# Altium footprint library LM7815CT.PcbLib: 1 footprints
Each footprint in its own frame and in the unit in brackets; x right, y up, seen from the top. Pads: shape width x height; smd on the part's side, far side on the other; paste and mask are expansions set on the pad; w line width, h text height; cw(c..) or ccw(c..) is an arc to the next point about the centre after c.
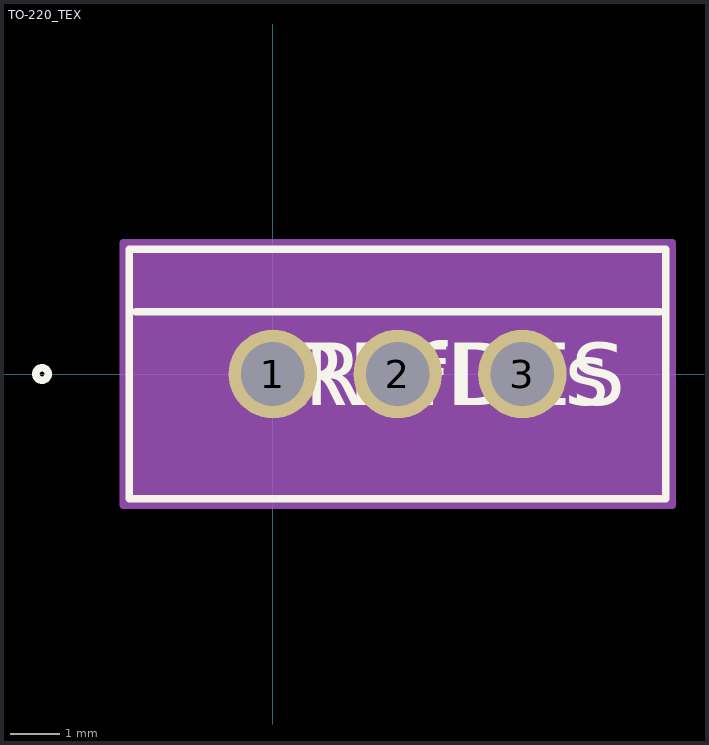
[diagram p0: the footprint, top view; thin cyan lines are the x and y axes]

## TO-220_TEX [mil]
pads (3):
  round 71 / inner round 60 / far side round 71 hole 51 paste-35.5 mask+0: 1(0,0) 2(100,0) 3(200,0)
Top Overlay:
  circle w6: c-185.04,0 r5
  lines w6: -110.04,50.08 310.04,50.08 ; -115.04,-100.08 315.04,-100.08 315.04,100.08 -115.04,100.08 -115.04,-100.08
  text "RefDes" at 25,-25 h50
  text "REFDES" at 12.5,-25 h50
Mechanical 13:
  circle w0: c-100.04,0 r5
  lines w1: -110.04,45.08 310.04,45.08 ; -110.04,-95.08 310.04,-95.08 310.04,95.08 -110.04,95.08 -110.04,-95.08
  text "TAB" at 81.25,57.58 h25
  text "RefDes2" at 12.5,-25 h50
Mechanical 15:
  region: 320.04,105.08 -120.04,105.08 -120.04,-105.08 320.04,-105.08
  lines w6: -120.04,-105.08 -120.04,105.08 320.04,105.08 320.04,-105.08 -120.04,-105.08
3D body "TO-220_TEX.step": height 650, standoff -350, extent -110.04,-95.08 310.04,95.08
